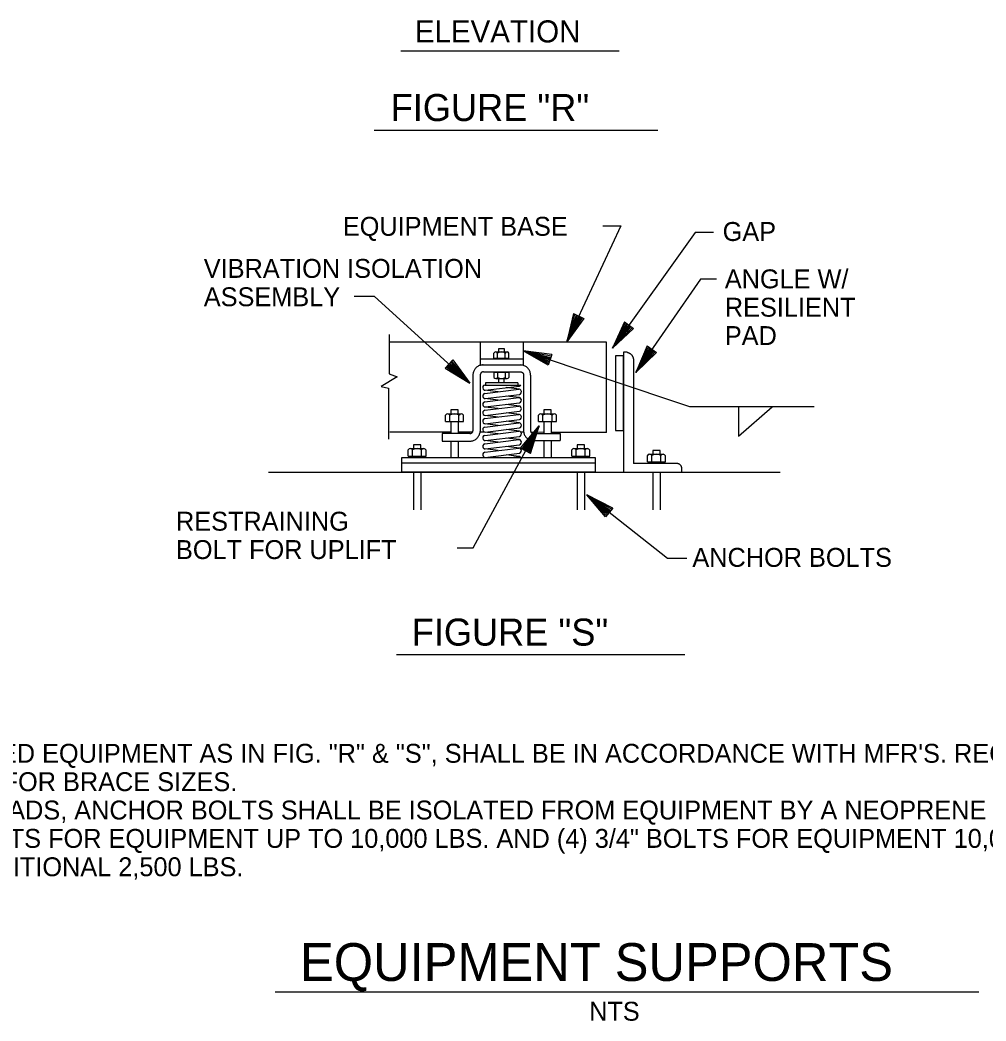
# Model space of a CAD drawing. Extents: x 9999.96 to 10005.26, y 9999.88 to 10002.38.
# Drawn here: x 10002.159 to 10002.67, y 10001.269 to 10001.799 of the extents above; entities that cross this region are included whole.
import ezdxf

# ---------------------------------------------------------------- set-up
doc = ezdxf.new("R2010")
doc.units = 0
doc.layers.add('Level 2', color=7, linetype='Continuous')

msp = doc.modelspace()

# ---------------------------------------------------------------- linework, layer by layer
at = {"layer": 'Level 2'}
for p, q in [((10002.36025, 10001.78246), (10002.47569, 10001.78246)), ((10002.34614, 10001.74067), (10002.49616, 10001.74067)), ((10002.45163, 10001.64357), (10002.44796, 10001.62867)), ((10002.44796, 10001.62867), (10002.45231, 10001.64325)), ((10002.44796, 10001.62867), (10002.45308, 10001.64292)), ((10002.45163, 10001.64357), (10002.45707, 10001.64101)), ((10002.44796, 10001.62867), (10002.45369, 10001.6426)), ((10002.45432, 10001.64232), (10002.44796, 10001.62867)), ((10002.44796, 10001.62867), (10002.455, 10001.64199)), ((10002.44796, 10001.62867), (10002.45569, 10001.64169)), ((10002.44796, 10001.62867), (10002.45633, 10001.64136)), ((10002.45707, 10001.64101), (10002.44796, 10001.62867)), ((10002.47845, 10001.63928), (10002.47213, 10001.62529)), ((10002.47213, 10001.62529), (10002.47907, 10001.63883)), ((10002.47213, 10001.62529), (10002.47977, 10001.63836)), ((10002.47213, 10001.62529), (10002.4803, 10001.63796)), ((10002.47845, 10001.63928), (10002.48334, 10001.63577)), ((10002.48088, 10001.63755), (10002.47213, 10001.62529)), ((10002.47213, 10001.62529), (10002.48148, 10001.6371)), ((10002.47213, 10001.62529), (10002.48209, 10001.63669)), ((10002.47213, 10001.62529), (10002.48268, 10001.63625)), ((10002.48334, 10001.63577), (10002.47213, 10001.62529)), ((10002.46894, 10001.62851), (10002.35444, 10001.62851)), ((10002.46894, 10001.58076), (10002.46894, 10001.62851)), ((10002.4095, 10001.61998), (10002.4095, 10001.62273)), ((10002.41049, 10001.62332), (10002.41641, 10001.62332)), ((10002.41146, 10001.61998), (10002.41146, 10001.62273)), ((10002.41543, 10001.61998), (10002.41543, 10001.62273)), ((10002.4174, 10001.61998), (10002.4174, 10001.62271)), ((10002.4249, 10001.62388), (10002.51285, 10001.5945)), ((10002.4392, 10001.61913), (10002.4249, 10001.62388)), ((10002.43821, 10001.61624), (10002.4249, 10001.62388)), ((10002.44013, 10001.62196), (10002.4249, 10001.62388)), ((10002.4249, 10001.62388), (10002.43872, 10001.6177)), ((10002.4249, 10001.62388), (10002.43964, 10001.62042)), ((10002.4249, 10001.62388), (10002.43848, 10001.61702)), ((10002.4249, 10001.62388), (10002.43895, 10001.61841)), ((10002.4249, 10001.62388), (10002.43941, 10001.61979)), ((10002.4249, 10001.62388), (10002.43989, 10001.62123)), ((10002.44013, 10001.62196), (10002.43821, 10001.61624)), ((10002.47809, 10001.62316), (10002.47809, 10001.55979)), ((10002.47993, 10001.62316), (10002.47809, 10001.62316)), ((10002.4906, 10001.62645), (10002.48449, 10001.61236)), ((10002.48449, 10001.61236), (10002.49123, 10001.62601)), ((10002.48449, 10001.61236), (10002.49194, 10001.62555)), ((10002.48449, 10001.61236), (10002.49247, 10001.62515)), ((10002.49305, 10001.62476), (10002.48449, 10001.61236)), ((10002.48449, 10001.61236), (10002.49367, 10001.62432)), ((10002.48449, 10001.61236), (10002.49429, 10001.62391)), ((10002.48449, 10001.61236), (10002.49488, 10001.62348)), ((10002.49554, 10001.623), (10002.48449, 10001.61236)), ((10002.4906, 10001.62645), (10002.49554, 10001.623)), ((10002.38366, 10001.61466), (10002.38773, 10001.6191)), ((10002.38566, 10001.61688), (10002.39681, 10001.60674)), ((10002.39681, 10001.60674), (10002.38618, 10001.61742)), ((10002.39681, 10001.60674), (10002.38668, 10001.61798)), ((10002.39681, 10001.60674), (10002.38717, 10001.61851)), ((10002.38773, 10001.6191), (10002.39681, 10001.60674)), ((10002.40227, 10001.61971), (10002.42517, 10001.61971)), ((10002.4095, 10001.61998), (10002.4174, 10001.61998)), ((10002.47372, 10001.62127), (10002.47372, 10001.5817)), ((10002.47809, 10001.62127), (10002.47372, 10001.62127)), ((10002.47809, 10001.5817), (10002.47809, 10001.62127)), ((10002.48326, 10001.61956), (10002.48326, 10001.56433)), ((10002.38366, 10001.61466), (10002.39681, 10001.60674)), ((10002.39681, 10001.60674), (10002.38418, 10001.61523)), ((10002.39681, 10001.60674), (10002.38473, 10001.61586)), ((10002.39681, 10001.60674), (10002.3852, 10001.61634)), ((10002.40225, 10001.61119), (10002.40225, 10001.58131)), ((10002.40392, 10001.61276), (10002.42353, 10001.61276)), ((10002.4095, 10001.61256), (10002.4174, 10001.61256)), ((10002.4095, 10001.61256), (10002.4095, 10001.60981)), ((10002.41146, 10001.61256), (10002.41146, 10001.60981)), ((10002.41543, 10001.61256), (10002.41543, 10001.60981)), ((10002.4174, 10001.61256), (10002.4174, 10001.60983)), ((10002.3984, 10001.61109), (10002.3984, 10001.58159)), ((10002.42205, 10001.60703), (10002.40502, 10001.60703)), ((10002.40502, 10001.60703), (10002.40502, 10001.60578)), ((10002.41049, 10001.60922), (10002.41641, 10001.60922)), ((10002.4119, 10001.60925), (10002.4119, 10001.60701)), ((10002.41494, 10001.60701), (10002.41494, 10001.60925)), ((10002.42205, 10001.60703), (10002.42205, 10001.60578)), ((10002.42515, 10001.61109), (10002.42515, 10001.58161)), ((10002.42884, 10001.61109), (10002.42884, 10001.58161)), ((10002.40465, 10001.60578), (10002.42376, 10001.60578)), ((10002.41167, 10001.60221), (10002.40465, 10001.60306)), ((10002.40466, 10001.60134), (10002.42269, 10001.60356)), ((10002.40492, 10001.60307), (10002.42294, 10001.60529)), ((10002.40493, 10001.59864), (10002.42296, 10001.60085)), ((10002.42295, 10001.60356), (10002.41592, 10001.60443)), ((10002.40465, 10001.59691), (10002.42267, 10001.59913)), ((10002.41168, 10001.59777), (10002.40467, 10001.59863)), ((10002.40492, 10001.5942), (10002.42294, 10001.59642)), ((10002.42295, 10001.59469), (10002.41592, 10001.59555)), ((10002.42297, 10001.59913), (10002.41593, 10001.59999)), ((10002.38505, 10001.5906), (10002.39222, 10001.5906)), ((10002.41167, 10001.59333), (10002.40465, 10001.59419)), ((10002.40465, 10001.58803), (10002.42267, 10001.59025)), ((10002.40466, 10001.59247), (10002.42269, 10001.59469)), ((10002.40493, 10001.58976), (10002.42296, 10001.59198)), ((10002.42297, 10001.59025), (10002.41593, 10001.59111)), ((10002.43425, 10001.5906), (10002.44142, 10001.5906)), ((10002.51285, 10001.5945), (10002.57879, 10001.5945)), ((10002.53874, 10001.59447), (10002.53874, 10001.57872)), ((10002.53874, 10001.57872), (10002.55653, 10001.59434)), ((10002.38385, 10001.58654), (10002.38385, 10001.58988)), ((10002.38385, 10001.58654), (10002.39341, 10001.58654)), ((10002.38622, 10001.58654), (10002.38622, 10001.58988)), ((10002.38668, 10001.58654), (10002.38668, 10001.58021)), ((10002.3906, 10001.58654), (10002.3906, 10001.58028)), ((10002.39102, 10001.58654), (10002.39102, 10001.58988)), ((10002.39341, 10001.58654), (10002.39341, 10001.58985)), ((10002.41167, 10001.58446), (10002.40465, 10001.58531)), ((10002.40466, 10001.58359), (10002.42269, 10001.58581)), ((10002.41168, 10001.5889), (10002.40467, 10001.58975)), ((10002.40492, 10001.58532), (10002.42294, 10001.58754)), ((10002.42295, 10001.58581), (10002.41592, 10001.58668)), ((10002.43305, 10001.58654), (10002.43305, 10001.58988)), ((10002.43305, 10001.58654), (10002.4426, 10001.58654)), ((10002.43542, 10001.58654), (10002.43542, 10001.58988)), ((10002.43588, 10001.58654), (10002.43588, 10001.58021)), ((10002.4398, 10001.58654), (10002.4398, 10001.58017)), ((10002.44022, 10001.58654), (10002.44022, 10001.58988)), ((10002.4426, 10001.58654), (10002.4426, 10001.58985)), ((10002.38668, 10001.58084), (10002.35444, 10001.58088)), ((10002.39678, 10001.58024), (10002.38207, 10001.58024)), ((10002.38207, 10001.58024), (10002.38207, 10001.5762)), ((10002.39816, 10001.58082), (10002.3906, 10001.58083)), ((10002.40474, 10001.58082), (10002.40215, 10001.58082)), ((10002.40465, 10001.57916), (10002.42267, 10001.58138)), ((10002.41168, 10001.58002), (10002.40467, 10001.58088)), ((10002.40493, 10001.58089), (10002.42296, 10001.5831)), ((10002.42297, 10001.58138), (10002.41593, 10001.58224)), ((10002.42354, 10001.57245), (10002.43334, 10001.58426)), ((10002.42522, 10001.5808), (10002.4238, 10001.5808)), ((10002.43334, 10001.58426), (10002.42426, 10001.57205)), ((10002.43334, 10001.58426), (10002.4249, 10001.5717)), ((10002.43334, 10001.58426), (10002.42555, 10001.57135)), ((10002.42622, 10001.57099), (10002.43334, 10001.58426)), ((10002.43334, 10001.58426), (10002.42683, 10001.57067)), ((10002.43334, 10001.58426), (10002.42742, 10001.57033)), ((10002.43334, 10001.58426), (10002.42817, 10001.56995)), ((10002.42884, 10001.56958), (10002.43334, 10001.58426)), ((10002.43588, 10001.58079), (10002.42908, 10001.5808)), ((10002.4303, 10001.58017), (10002.44443, 10001.58017)), ((10002.46894, 10001.58076), (10002.4398, 10001.58079)), ((10002.44443, 10001.58014), (10002.44443, 10001.57653)), ((10002.47372, 10001.5817), (10002.47809, 10001.5817)), ((10002.38207, 10001.57615), (10002.39656, 10001.57615)), ((10002.38668, 10001.57615), (10002.38668, 10001.56757)), ((10002.3906, 10001.57615), (10002.3906, 10001.56757)), ((10002.41167, 10001.57557), (10002.40465, 10001.57644)), ((10002.40466, 10001.57472), (10002.42269, 10001.57693)), ((10002.40492, 10001.57645), (10002.42294, 10001.57866)), ((10002.40493, 10001.57201), (10002.42296, 10001.57422)), ((10002.42295, 10001.57693), (10002.41592, 10001.57779)), ((10002.43041, 10001.57648), (10002.44443, 10001.57648)), ((10002.43588, 10001.57648), (10002.43588, 10001.56757)), ((10002.4398, 10001.57648), (10002.4398, 10001.56757)), ((10002.3641, 10001.56814), (10002.3641, 10001.57147)), ((10002.3653, 10001.5722), (10002.37247, 10001.5722)), ((10002.36647, 10001.56814), (10002.36647, 10001.57147)), ((10002.37127, 10001.56814), (10002.37127, 10001.57147)), ((10002.37366, 10001.56814), (10002.37366, 10001.57145)), ((10002.40465, 10001.57028), (10002.42267, 10001.57249)), ((10002.41168, 10001.57114), (10002.40467, 10001.572)), ((10002.40492, 10001.56757), (10002.42294, 10001.56978)), ((10002.42268, 10001.56809), (10002.41592, 10001.56892)), ((10002.42297, 10001.57249), (10002.41593, 10001.57335)), ((10002.42884, 10001.56958), (10002.42354, 10001.57245)), ((10002.45063, 10001.56814), (10002.45063, 10001.57147)), ((10002.45182, 10001.5722), (10002.45899, 10001.5722)), ((10002.45299, 10001.56814), (10002.45299, 10001.57147)), ((10002.45779, 10001.56814), (10002.45779, 10001.57147)), ((10002.46018, 10001.56814), (10002.46018, 10001.57145)), ((10002.49181, 10001.56919), (10002.49898, 10001.56919)), ((10002.36077, 10001.56463), (10002.4631, 10001.56463)), ((10002.3641, 10001.56814), (10002.37366, 10001.56814)), ((10002.41843, 10001.56757), (10002.42268, 10001.56809)), ((10002.45063, 10001.56814), (10002.46018, 10001.56814)), ((10002.5062, 10001.56433), (10002.48326, 10001.56433)), ((10002.49061, 10001.56513), (10002.49061, 10001.56846)), ((10002.49061, 10001.56513), (10002.50017, 10001.56513)), ((10002.49298, 10001.56513), (10002.49298, 10001.56846)), ((10002.49778, 10001.56513), (10002.49778, 10001.56846)), ((10002.50017, 10001.56513), (10002.50017, 10001.56844)), ((10002.29031, 10001.55979), (10002.5608, 10001.55979)), ((10002.36693, 10001.5598), (10002.36693, 10001.53982)), ((10002.37085, 10001.5598), (10002.37085, 10001.53982)), ((10002.45345, 10001.5598), (10002.45345, 10001.53982)), ((10002.45738, 10001.5598), (10002.45738, 10001.53982)), ((10002.47809, 10001.55979), (10002.50892, 10001.55979)), ((10002.49344, 10001.5598), (10002.49344, 10001.53982)), ((10002.49736, 10001.5598), (10002.49736, 10001.53982)), ((10002.50892, 10001.55979), (10002.50892, 10001.56147)), ((10002.47047, 10001.53841), (10002.45864, 10001.54773)), ((10002.46857, 10001.53603), (10002.45864, 10001.54773)), ((10002.47231, 10001.54076), (10002.45864, 10001.54773)), ((10002.45864, 10001.54773), (10002.46954, 10001.53723)), ((10002.45864, 10001.54773), (10002.47133, 10001.53948)), ((10002.45864, 10001.54773), (10002.46908, 10001.53667)), ((10002.45864, 10001.54773), (10002.47, 10001.53782)), ((10002.45864, 10001.54773), (10002.4709, 10001.53897)), ((10002.45864, 10001.54773), (10002.47183, 10001.54016)), ((10002.47231, 10001.54076), (10002.46857, 10001.53603)), ((10002.35799, 10001.46327), (10002.51045, 10001.46327)), ((10002.29384, 10001.28491), (10002.66585, 10001.28491))]:
    msp.add_line(p, q, dxfattribs=at)
for points in [[(10002.46707, 10001.68993), (10002.47663, 10001.68993), (10002.44796, 10001.62867)], [(10002.52552, 10001.68656), (10002.51597, 10001.68656), (10002.47213, 10001.62529)], [(10002.52721, 10001.66182), (10002.51878, 10001.66182), (10002.48449, 10001.61236)], [(10002.33554, 10001.65283), (10002.34622, 10001.65283), (10002.39681, 10001.60674)], [(10002.35408, 10001.63258), (10002.35408, 10001.61179), (10002.35829, 10001.6101), (10002.34986, 10001.60504), (10002.3538, 10001.6042), (10002.3538, 10001.57722)], [(10002.41507, 10001.62334), (10002.41507, 10001.625), (10002.41183, 10001.625), (10002.41183, 10001.62334)], [(10002.47993, 10001.62316), (10002.48011, 10001.6231), (10002.48031, 10001.62305), (10002.4805, 10001.62299), (10002.48069, 10001.62292), (10002.48086, 10001.62283), (10002.48104, 10001.62274), (10002.48122, 10001.62265), (10002.48139, 10001.62254), (10002.48155, 10001.62243), (10002.48171, 10001.6223), (10002.48186, 10001.62218), (10002.48201, 10001.62203), (10002.48215, 10001.6219), (10002.48228, 10001.62175), (10002.48241, 10001.62159), (10002.48252, 10001.62143), (10002.48264, 10001.62126), (10002.48274, 10001.62109), (10002.48283, 10001.62092), (10002.48292, 10001.62074), (10002.483, 10001.62055), (10002.48306, 10001.62036), (10002.48313, 10001.62018), (10002.48318, 10001.61999), (10002.48327, 10001.61956)], [(10002.40385, 10001.61646), (10002.40344, 10001.61645), (10002.40301, 10001.6164), (10002.4026, 10001.61631), (10002.4022, 10001.6162), (10002.40171, 10001.61605), (10002.40132, 10001.61588), (10002.40096, 10001.61567), (10002.4006, 10001.61544), (10002.40027, 10001.61518), (10002.39997, 10001.61489), (10002.39968, 10001.61458), (10002.39942, 10001.61425), (10002.39919, 10001.6139), (10002.39898, 10001.61353), (10002.3988, 10001.61315), (10002.39866, 10001.61275), (10002.39854, 10001.61234), (10002.39846, 10001.61194), (10002.39841, 10001.61152), (10002.3984, 10001.61109)], [(10002.42884, 10001.61109), (10002.42882, 10001.61151), (10002.42877, 10001.61193), (10002.4287, 10001.61233), (10002.42858, 10001.61274), (10002.42844, 10001.61314), (10002.42826, 10001.61351), (10002.42806, 10001.61388), (10002.42782, 10001.61422), (10002.42756, 10001.61455), (10002.42728, 10001.61485), (10002.42698, 10001.61514), (10002.42665, 10001.6154), (10002.4263, 10001.61563), (10002.42594, 10001.61583), (10002.42556, 10001.61601), (10002.42517, 10001.61616), (10002.42476, 10001.61626), (10002.42435, 10001.61634), (10002.42394, 10001.6164), (10002.42352, 10001.61642)], [(10002.40392, 10001.61276), (10002.40378, 10001.61275), (10002.40366, 10001.61274), (10002.40352, 10001.61272), (10002.4034, 10001.61268), (10002.40327, 10001.61264), (10002.40316, 10001.61257), (10002.40304, 10001.61251), (10002.40294, 10001.61244), (10002.40283, 10001.61236), (10002.40273, 10001.61227), (10002.40265, 10001.61218), (10002.40256, 10001.61207), (10002.40249, 10001.61196), (10002.40243, 10001.61184), (10002.40238, 10001.61173), (10002.40232, 10001.6116), (10002.40229, 10001.61148), (10002.40227, 10001.61135), (10002.40225, 10001.61122), (10002.40225, 10001.61119)], [(10002.42353, 10001.61276), (10002.42366, 10001.61276), (10002.42378, 10001.61274), (10002.42391, 10001.61272), (10002.42403, 10001.61269), (10002.42416, 10001.61265), (10002.42427, 10001.61259), (10002.42439, 10001.61253), (10002.42449, 10001.61246), (10002.42459, 10001.61239), (10002.42469, 10001.61229), (10002.42477, 10001.6122), (10002.42485, 10001.6121), (10002.42493, 10001.612), (10002.42499, 10001.61189), (10002.42504, 10001.61177), (10002.42509, 10001.61165), (10002.42513, 10001.61152), (10002.42515, 10001.6114), (10002.42517, 10001.61127), (10002.42517, 10001.61115)], [(10002.3906, 10001.59063), (10002.3906, 10001.59263), (10002.38668, 10001.59263), (10002.38668, 10001.59063)], [(10002.4398, 10001.59063), (10002.4398, 10001.59263), (10002.43588, 10001.59263), (10002.43588, 10001.59063)], [(10002.39006, 10001.51963), (10002.3985, 10001.51963), (10002.43334, 10001.58426)], [(10002.39656, 10001.57615), (10002.39701, 10001.57616), (10002.39745, 10001.57619), (10002.39788, 10001.57626), (10002.3983, 10001.57636), (10002.39872, 10001.57651), (10002.39913, 10001.57668), (10002.39952, 10001.57689), (10002.39989, 10001.57711), (10002.40024, 10001.57739), (10002.40057, 10001.57768), (10002.40088, 10001.57799), (10002.40116, 10001.57833), (10002.40136, 10001.5787), (10002.40158, 10001.57907), (10002.40178, 10001.57947), (10002.40194, 10001.57989), (10002.40206, 10001.5803), (10002.40215, 10001.58074), (10002.40221, 10001.58117), (10002.40221, 10001.58126)], [(10002.39678, 10001.58024), (10002.39691, 10001.58023), (10002.39702, 10001.58023), (10002.39715, 10001.58023), (10002.39726, 10001.58025), (10002.39738, 10001.58028), (10002.39749, 10001.58032), (10002.39759, 10001.58036), (10002.39771, 10001.58043), (10002.3978, 10001.58049), (10002.3979, 10001.58056), (10002.39799, 10001.58065), (10002.39806, 10001.58073), (10002.39814, 10001.58082), (10002.39821, 10001.58093), (10002.39826, 10001.58103), (10002.3983, 10001.58115), (10002.39834, 10001.58126), (10002.39838, 10001.58138), (10002.39839, 10001.58149), (10002.39839, 10001.58153)], [(10002.42515, 10001.58161), (10002.42517, 10001.5812), (10002.42522, 10001.5808), (10002.4253, 10001.5804), (10002.42542, 10001.58), (10002.42556, 10001.57963), (10002.42573, 10001.57925), (10002.42594, 10001.5789), (10002.42617, 10001.57856), (10002.42643, 10001.57824), (10002.42671, 10001.57795), (10002.42701, 10001.57767), (10002.42733, 10001.57743), (10002.42768, 10001.5772), (10002.42803, 10001.57701), (10002.42841, 10001.57684), (10002.42879, 10001.57671), (10002.42919, 10001.5766), (10002.42959, 10001.57653), (10002.43, 10001.57649), (10002.43041, 10001.57648)], [(10002.42884, 10001.58161), (10002.42884, 10001.58149), (10002.42886, 10001.58138), (10002.4289, 10001.58126), (10002.42893, 10001.58115), (10002.42897, 10001.58103), (10002.42902, 10001.58093), (10002.42908, 10001.58082), (10002.42916, 10001.58073), (10002.42924, 10001.58064), (10002.42932, 10001.58055), (10002.42942, 10001.58048), (10002.42951, 10001.58041), (10002.42961, 10001.58034), (10002.42972, 10001.58029), (10002.42983, 10001.58025), (10002.42995, 10001.58022), (10002.43006, 10001.58019), (10002.43018, 10001.58018), (10002.4303, 10001.58017), (10002.43042, 10001.58017)], [(10002.37085, 10001.57222), (10002.37085, 10001.57422), (10002.36693, 10001.57422), (10002.36693, 10001.57222)], [(10002.45738, 10001.57222), (10002.45738, 10001.57422), (10002.45345, 10001.57422), (10002.45345, 10001.57222)], [(10002.49736, 10001.56921), (10002.49736, 10001.57121), (10002.49344, 10001.57121), (10002.49344, 10001.56921)], [(10002.5089, 10001.56126), (10002.50891, 10001.56145), (10002.50891, 10001.56165), (10002.50889, 10001.56183), (10002.50885, 10001.56203), (10002.50881, 10001.56222), (10002.50875, 10001.56241), (10002.50869, 10001.56258), (10002.5086, 10001.56276), (10002.50851, 10001.56294), (10002.50841, 10001.56309), (10002.50829, 10001.56325), (10002.50817, 10001.56341), (10002.50803, 10001.56354), (10002.50789, 10001.56367), (10002.50773, 10001.56379), (10002.50757, 10001.5639), (10002.5074, 10001.564), (10002.50723, 10001.56408), (10002.50704, 10001.56416), (10002.50686, 10001.56422), (10002.50668, 10001.56427), (10002.50648, 10001.5643), (10002.50629, 10001.56433), (10002.5062, 10001.56433)], [(10002.51147, 10001.514), (10002.50135, 10001.514), (10002.45864, 10001.54773)]]:
    msp.add_lwpolyline(points, dxfattribs=at)
for points in [[(10002.40226, 10001.62851), (10002.40226, 10001.61646), (10002.42517, 10001.61646), (10002.42517, 10001.62851)], [(10002.36077, 10001.5598), (10002.36077, 10001.56757), (10002.4631, 10001.56757), (10002.4631, 10001.5598)]]:
    msp.add_lwpolyline(points, close=True, dxfattribs=at)
for centre, radius, start, end in [((10002.41048, 10001.62222), 0.0011, 27.8877, 152.0342), ((10002.41344, 10001.61968), 0.00365, 57.0062, 122.943), ((10002.4164, 10001.62221), 0.0011, 26.7827, 151.8391), ((10002.41048, 10001.61032), 0.0011, 207.9658, 332.1123), ((10002.41344, 10001.61286), 0.00365, 237.057, 302.9938), ((10002.4164, 10001.61033), 0.0011, 208.1609, 333.2173), ((10002.38504, 10001.58926), 0.00134, 27.8877, 152.0342), ((10002.38863, 10001.58618), 0.00441, 57.0062, 122.943), ((10002.39221, 10001.58925), 0.00134, 26.7827, 151.8391), ((10002.43424, 10001.58926), 0.00134, 27.8877, 152.0342), ((10002.43782, 10001.58618), 0.00441, 57.0062, 122.943), ((10002.44141, 10001.58925), 0.00134, 26.7827, 151.8391), ((10002.36529, 10001.57085), 0.00134, 27.8877, 152.0342), ((10002.36888, 10001.56778), 0.00441, 57.0062, 122.943), ((10002.37246, 10001.57084), 0.00134, 26.7827, 151.8391), ((10002.45182, 10001.57085), 0.00134, 27.8877, 152.0342), ((10002.4554, 10001.56778), 0.00441, 57.0062, 122.943), ((10002.45898, 10001.57084), 0.00134, 26.7827, 151.8391), ((10002.49181, 10001.56784), 0.00134, 27.8877, 152.0342), ((10002.49539, 10001.56477), 0.00441, 57.0062, 122.943), ((10002.49897, 10001.56783), 0.00134, 26.7827, 151.8391)]:
    msp.add_arc(centre, radius, start, end, dxfattribs=at)
for centre, major_axis, start_param, end_param in [((10002.40478, 10001.60442), (0, -0.00136), 3.251722, 6.393315), ((10002.4048, 10001.59998), (0, -0.00136), 3.251722, 6.393315), ((10002.42282, 10001.6022), (0, 0.00136), 3.251722, 6.393315), ((10002.4228, 10001.60664), (0, 0.00136), 3.251722, 4.030489), ((10002.40478, 10001.59555), (0, -0.00136), 3.251722, 6.393315), ((10002.4228, 10001.59776), (0, 0.00136), 3.251722, 6.393315), ((10002.4048, 10001.59111), (0, -0.00136), 3.251722, 6.393315), ((10002.4228, 10001.58889), (0, 0.00136), 3.251722, 6.393315), ((10002.42282, 10001.59333), (0, 0.00136), 3.251722, 6.393315), ((10002.40478, 10001.58667), (0, -0.00136), 3.251722, 6.393315), ((10002.42282, 10001.58445), (0, 0.00136), 3.251722, 6.393315), ((10002.4048, 10001.58223), (0, -0.00136), 3.251722, 6.393315), ((10002.4228, 10001.58001), (0, 0.00136), 3.251722, 6.393315), ((10002.40478, 10001.5778), (0, -0.00136), 3.251722, 6.393315), ((10002.4048, 10001.57336), (0, -0.00136), 3.251722, 6.393315), ((10002.42282, 10001.57558), (0, 0.00136), 3.251722, 6.393315), ((10002.40478, 10001.56892), (0, -0.00136), 3.251722, 6.393315), ((10002.4228, 10001.57114), (0, 0.00136), 3.251722, 6.393315), ((10002.42268, 10001.56673), (0, 0.00136), 5.361733, 6.39416)]:
    msp.add_ellipse(centre, major_axis=major_axis, ratio=0.9, start_param=start_param, end_param=end_param, dxfattribs=at)

# ---------------------------------------------------------------- texts
for s, height, p in [('ELEVATION', 0.011667, (10002.36767, 10001.787)), ('FIGURE "R"', 0.014301, (10002.35491, 10001.74541)), ('EQUIPMENT BASE', 0.01, (10002.32961, 10001.68474)), ('GAP ', 0.01, (10002.53043, 10001.682)), ('VIBRATION ISOLATION', 0.01, (10002.25609, 10001.66248)), ('ANGLE W/', 0.01, (10002.53158, 10001.65695)), ('ASSEMBLY', 0.01, (10002.25609, 10001.64748)), ('RESILIENT ', 0.01, (10002.53158, 10001.64195)), ('PAD', 0.01, (10002.53158, 10001.62695)), ('RESTRAINING', 0.01, (10002.24139, 10001.52879)), ('BOLT FOR UPLIFT', 0.01, (10002.24139, 10001.51379)), ('ANCHOR BOLTS', 0.01, (10002.51443, 10001.50966)), ('FIGURE "S"', 0.014301, (10002.36604, 10001.468)), ('1. CLEARANCES AT SIDES FOR SPRING MOUNTED EQUIPMENT AS IN FIG. "R" & "S", SHALL BE IN ACCORDANCE WITH MFR\'S. RECOMMENDATIONS.', 0.01, (10001.83844, 10001.40605)), ('2. SEE MAXIMUM BRACING LENGTHS, TABLE 1, FOR BRACE SIZES.', 0.01, (10001.83986, 10001.39105)), ('3. IF EQUIPMENT IS MOUNTED ON NEOPRENE PADS, ANCHOR BOLTS SHALL BE ISOLATED FROM EQUIPMENT BY A NEOPRENE SLEEVE AND WASHER.', 0.01, (10001.83986, 10001.37605)), ('4. PROVIDE A MINIMUM OF (4) 1/2" ANCHOR BOLTS FOR EQUIPMENT UP TO 10,000 LBS. AND (4) 3/4" BOLTS FOR EQUIPMENT 10,000 LBS. OR GREATER.', 0.01, (10001.83986, 10001.36105)), ('   ADD (1) ADDITIONAL 3/4" BOLT FOR EACH ADDITIONAL 2,500 LBS.', 0.01, (10001.8413, 10001.34605)), ('EQUIPMENT SUPPORTS', 0.02, (10002.30696, 10001.29066)), ('NTS', 0.01, (10002.45982, 10001.26964))]:
    msp.add_text(s, height=height, dxfattribs=at).set_placement(p)

doc.saveas('drawing.dxf')
